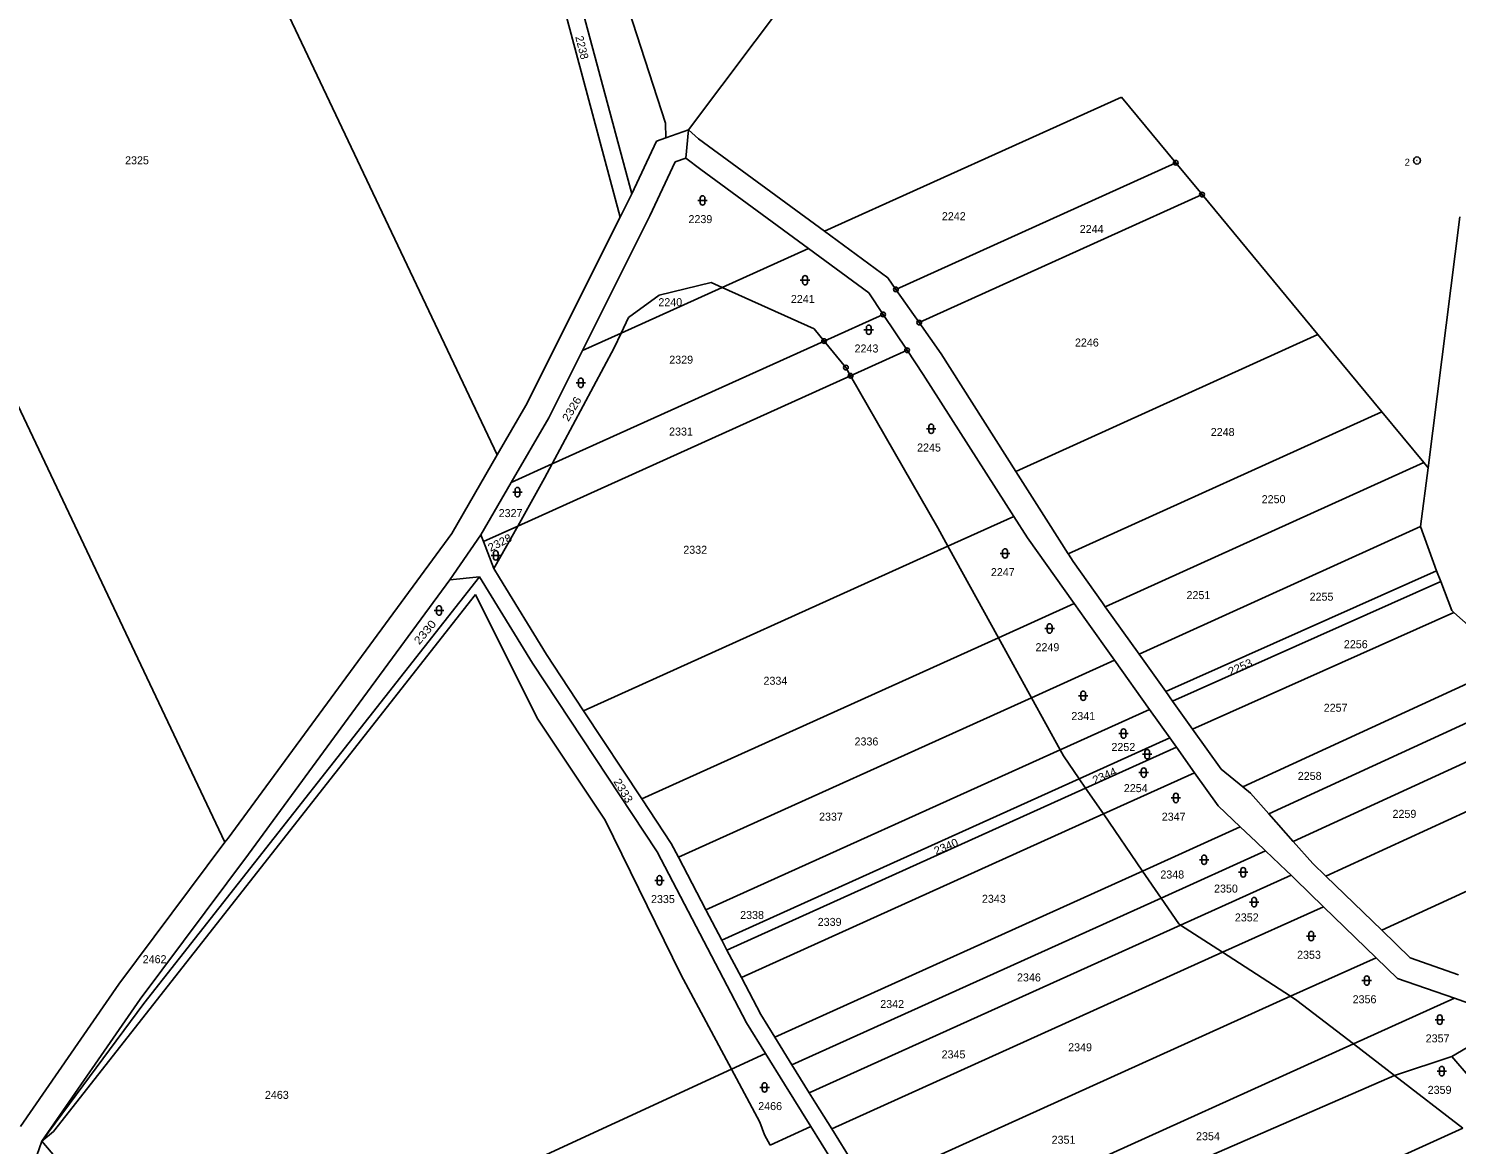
# Model space of a CAD drawing. Extents: x -606517 to -602431, y -1183120 to -1179397.
# Drawn here: x -605326.3 to -605022.9, y -1180737.7 to -1180500.6 of the extents above; entities that cross this region are included whole.
import ezdxf
from ezdxf.enums import TextEntityAlignment as Align

# ---------------------------------------------------------------- set-up
doc = ezdxf.new("R2010")
doc.units = 0
doc.header["$LTSCALE"] = 0.68
for name, color, linetype, lineweight in [('1', 7, 'Continuous', 25), ('3', 7, 'Continuous', 25), ('8', 7, 'Continuous', 25)]:
    doc.layers.add(name, color=color, linetype=linetype, lineweight=lineweight)
doc.layers.add('2', color=7, linetype='Continuous')

msp = doc.modelspace()

# ---------------------------------------------------------------- linework, layer by layer
at = {"layer": '1'}
for p, q in [((-605226.69, -1180591.17), (-605304.36, -1180427.32)), ((-605126.51, -1180442.54), (-605186.02, -1180522.13)), ((-605190.97, -1180520.67), (-605210.04, -1180461.72)), ((-605219.84, -1180468.76), (-605200.54, -1180540.66)), ((-605198.12, -1180535.69), (-605208.88, -1180495.66)), ((-605094.07, -1180515.16), (-605157.16, -1180543.67)), ((-605082.54, -1180529.1), (-605094.07, -1180515.16)), ((-605190.84, -1180523.78), (-605190.97, -1180520.67)), ((-605190.84, -1180523.78), (-605192.87, -1180524.48)), ((-605186.02, -1180522.13), (-605190.84, -1180523.78)), ((-605186.64, -1180528.15), (-605186.02, -1180522.13)), ((-605186.02, -1180522.13), (-605183.96, -1180523.98)), ((-605183.96, -1180523.98), (-605157.16, -1180543.67)), ((-605192.87, -1180524.48), (-605198.12, -1180535.69)), ((-605188.88, -1180528.92), (-605194.26, -1180540.41)), ((-605186.64, -1180528.15), (-605188.88, -1180528.92)), ((-605183.45, -1180530.5), (-605186.64, -1180528.15)), ((-605141.99, -1180556.01), (-605082.54, -1180529.1)), ((-605082.54, -1180529.1), (-605076.96, -1180535.85)), ((-605160.59, -1180547.32), (-605183.45, -1180530.5)), ((-605200.54, -1180540.66), (-605198.12, -1180535.69)), ((-605137.04, -1180563.05), (-605076.96, -1180535.85)), ((-605076.96, -1180535.85), (-605052.33, -1180565.62)), ((-605200.54, -1180540.66), (-605220.6, -1180580.66)), ((-605194.26, -1180540.41), (-605208.6, -1180569.01)), ((-605028.93, -1180593.91), (-605022.19, -1180540.62)), ((-605157.16, -1180543.67), (-605143.74, -1180553.52)), ((-605160.59, -1180547.32), (-605178.9, -1180555.59)), ((-605147.75, -1180556.77), (-605160.59, -1180547.32)), ((-605143.74, -1180553.52), (-605141.99, -1180556.01)), ((-605178.9, -1180555.59), (-605200.39, -1180565.3)), ((-605192.28, -1180557.21), (-605198.81, -1180561.95)), ((-605181.25, -1180554.53), (-605192.28, -1180557.21)), ((-605178.9, -1180555.59), (-605181.25, -1180554.53)), ((-605159.35, -1180564.41), (-605178.9, -1180555.59)), ((-605144.71, -1180561.33), (-605147.75, -1180556.77)), ((-605137.04, -1180563.05), (-605141.99, -1180556.01)), ((-605284.53, -1180673.49), (-605337.03, -1180562.74)), ((-605198.81, -1180561.95), (-605200.39, -1180565.3)), ((-605144.71, -1180561.33), (-605157.24, -1180566.99)), ((-605139.63, -1180568.93), (-605144.71, -1180561.33)), ((-605132.37, -1180569.7), (-605137.04, -1180563.05)), ((-605208.6, -1180569.01), (-605200.39, -1180565.3)), ((-605200.39, -1180565.3), (-605201.85, -1180568.41)), ((-605157.24, -1180566.99), (-605159.35, -1180564.41)), ((-605116.52, -1180594.68), (-605052.33, -1180565.62)), ((-605052.33, -1180565.62), (-605038.75, -1180582.03)), ((-605208.6, -1180569.01), (-605215.76, -1180583.28)), ((-605157.24, -1180566.99), (-605215.03, -1180593.1)), ((-605201.85, -1180568.41), (-605215.03, -1180593.1)), ((-605152.62, -1180572.62), (-605157.24, -1180566.99)), ((-605139.63, -1180568.93), (-605151.63, -1180574.35)), ((-605136.18, -1180574.09), (-605139.63, -1180568.93)), ((-605151.63, -1180574.35), (-605152.62, -1180572.62)), ((-605116.52, -1180594.68), (-605132.37, -1180569.7)), ((-605151.63, -1180574.35), (-605222.33, -1180606.29)), ((-605133.11, -1180606.66), (-605151.63, -1180574.35)), ((-605116.94, -1180604.27), (-605136.18, -1180574.09)), ((-605220.6, -1180580.66), (-605226.69, -1180591.17)), ((-605215.76, -1180583.28), (-605223.71, -1180597.02)), ((-605105.38, -1180612.2), (-605038.75, -1180582.03)), ((-605038.75, -1180582.03), (-605029.84, -1180592.8)), ((-605226.69, -1180591.17), (-605236.37, -1180607.9)), ((-605215.03, -1180593.1), (-605223.71, -1180597.02)), ((-605215.03, -1180593.1), (-605216.63, -1180596.09)), ((-605097.5, -1180623.43), (-605029.84, -1180592.8)), ((-605028.93, -1180593.91), (-605030.52, -1180606.42)), ((-605029.84, -1180592.8), (-605028.93, -1180593.91)), ((-605216.63, -1180596.09), (-605222.33, -1180606.29)), ((-605109.56, -1180605.64), (-605116.52, -1180594.68)), ((-605223.71, -1180597.02), (-605230.17, -1180608.18)), ((-605116.94, -1180604.27), (-605130.94, -1180610.59)), ((-605114.03, -1180608.83), (-605116.94, -1180604.27)), ((-605105.38, -1180612.2), (-605109.56, -1180605.64)), ((-605236.37, -1180607.9), (-605260.43, -1180640.69)), ((-605236.73, -1180617.7), (-605230.17, -1180608.18)), ((-605230.17, -1180608.18), (-605229.63, -1180609.59)), ((-605229.63, -1180609.59), (-605222.33, -1180606.29)), ((-605222.33, -1180606.29), (-605227.39, -1180615.34)), ((-605130.94, -1180610.59), (-605133.11, -1180606.66)), ((-605104.11, -1180622.77), (-605114.03, -1180608.83)), ((-605030.52, -1180606.42), (-605090.33, -1180633.5)), ((-605030.52, -1180606.42), (-605027.12, -1180615.83)), ((-605229.63, -1180609.59), (-605227.39, -1180615.34)), ((-605208.33, -1180645.55), (-605130.94, -1180610.59)), ((-605130.94, -1180610.59), (-605120.21, -1180630.04)), ((-605105.35, -1180612.24), (-605105.38, -1180612.2)), ((-605104.35, -1180613.81), (-605105.35, -1180612.24)), ((-605098.08, -1180622.62), (-605104.35, -1180613.81)), ((-605301.78, -1180707.72), (-605230.45, -1180617.06)), ((-605236.73, -1180617.7), (-605255.99, -1180643.95)), ((-605230.45, -1180617.06), (-605236.73, -1180617.7)), ((-605230.45, -1180617.06), (-605219.17, -1180635.46)), ((-605227.39, -1180615.34), (-605226.18, -1180617.32)), ((-605226.18, -1180617.32), (-605216.22, -1180633.58)), ((-605084.65, -1180641.48), (-605027.12, -1180615.83)), ((-605083.21, -1180643.51), (-605026.25, -1180618.11)), ((-605027.12, -1180615.83), (-605026.25, -1180618.11)), ((-605026.25, -1180618.11), (-605023.91, -1180624.27)), ((-605231.28, -1180620.82), (-605320.99, -1180734.92)), ((-605218.18, -1180647.1), (-605231.28, -1180620.82)), ((-605104.11, -1180622.77), (-605120.21, -1180630.04)), ((-605101.68, -1180626.18), (-605104.11, -1180622.77)), ((-605097.5, -1180623.43), (-605098.08, -1180622.62)), ((-605090.33, -1180633.5), (-605097.5, -1180623.43)), ((-605023.91, -1180624.27), (-605023.45, -1180624.68)), ((-605095.55, -1180634.79), (-605101.68, -1180626.18)), ((-605078.98, -1180649.44), (-605023.45, -1180624.68)), ((-605023.45, -1180624.68), (-605011.3, -1180635.5)), ((-605120.21, -1180630.04), (-605195.98, -1180664.27)), ((-605113.19, -1180642.76), (-605120.21, -1180630.04)), ((-605219.17, -1180635.46), (-605192.74, -1180675.55)), ((-605216.22, -1180633.58), (-605208.33, -1180645.55)), ((-605113.19, -1180642.76), (-605095.55, -1180634.79)), ((-605088.1, -1180645.27), (-605095.55, -1180634.79)), ((-605084.65, -1180641.48), (-605090.33, -1180633.5)), ((-605068.31, -1180661.72), (-605011.3, -1180635.5)), ((-605260.43, -1180640.69), (-605283.88, -1180672.63)), ((-605083.21, -1180643.51), (-605084.65, -1180641.48)), ((-605062.78, -1180667.45), (-605005.17, -1180640.96)), ((-605255.99, -1180643.95), (-605279.53, -1180676.02)), ((-605113.19, -1180642.76), (-605188.21, -1180676.65)), ((-605107.08, -1180653.84), (-605113.19, -1180642.76)), ((-605088.1, -1180645.27), (-605107.08, -1180653.84)), ((-605083.79, -1180651.32), (-605088.1, -1180645.27)), ((-605078.98, -1180649.44), (-605083.21, -1180643.51)), ((-605203.78, -1180668.79), (-605218.18, -1180647.1)), ((-605208.33, -1180645.55), (-605195.98, -1180664.27)), ((-605057.57, -1180673.32), (-604999.05, -1180646.41)), ((-605083.79, -1180651.32), (-605103.03, -1180660.01)), ((-605082.41, -1180653.26), (-605083.79, -1180651.32)), ((-605072.92, -1180657.96), (-605078.98, -1180649.44)), ((-605182.35, -1180687.85), (-605107.08, -1180653.84)), ((-605107.08, -1180653.84), (-605106.37, -1180655.13)), ((-605082.41, -1180653.26), (-605101.68, -1180661.97)), ((-605078.53, -1180658.71), (-605082.41, -1180653.26)), ((-605050.64, -1180680.69), (-604991.23, -1180653.38)), ((-605106.37, -1180655.13), (-605103.03, -1180660.01)), ((-605103.03, -1180660.01), (-605178.97, -1180694.32)), ((-605103.03, -1180660.01), (-605101.68, -1180661.97)), ((-605097.91, -1180667.47), (-605078.53, -1180658.71)), ((-605073.54, -1180665.72), (-605078.53, -1180658.71)), ((-605068.31, -1180661.72), (-605072.92, -1180657.96)), ((-605101.68, -1180661.97), (-605177.88, -1180696.39)), ((-605097.91, -1180667.47), (-605101.68, -1180661.97)), ((-605066.66, -1180663.07), (-605068.31, -1180661.72)), ((-605062.78, -1180667.45), (-605066.66, -1180663.07)), ((-605195.98, -1180664.27), (-605189.72, -1180673.77)), ((-605068.82, -1180670.22), (-605073.54, -1180665.72)), ((-605038.77, -1180692.19), (-604978.67, -1180664.56)), ((-605187.67, -1180701.61), (-605203.78, -1180668.79)), ((-605174.83, -1180702.22), (-605097.91, -1180667.47)), ((-605089.59, -1180679.61), (-605097.91, -1180667.47)), ((-605057.57, -1180673.32), (-605062.78, -1180667.45)), ((-605283.88, -1180672.63), (-605284.53, -1180673.49)), ((-605068.82, -1180670.22), (-605089.59, -1180679.61)), ((-605065.47, -1180673.41), (-605068.82, -1180670.22)), ((-605307.05, -1180703.62), (-605284.53, -1180673.49)), ((-605192.74, -1180675.55), (-605173.75, -1180711.84)), ((-605189.72, -1180673.77), (-605188.21, -1180676.65)), ((-605063.46, -1180675.33), (-605065.47, -1180673.41)), ((-605059, -1180679.57), (-605063.46, -1180675.33)), ((-605053.45, -1180677.97), (-605057.57, -1180673.32)), ((-605279.53, -1180676.02), (-605302.56, -1180706.8)), ((-605188.21, -1180676.65), (-605182.35, -1180687.85)), ((-605050.64, -1180680.69), (-605053.45, -1180677.97)), ((-605089.59, -1180679.61), (-605167.72, -1180714.91)), ((-605085.65, -1180685.35), (-605089.59, -1180679.61)), ((-605058.05, -1180680.48), (-605059, -1180679.57)), ((-605057.18, -1180681.31), (-605058.05, -1180680.48)), ((-605051.13, -1180687.17), (-605057.18, -1180681.31)), ((-605038.77, -1180692.19), (-605050.64, -1180680.69)), ((-605182.35, -1180687.85), (-605178.97, -1180694.32)), ((-605081.89, -1180690.84), (-605085.65, -1180685.35)), ((-605051.13, -1180687.17), (-605072.59, -1180696.86)), ((-605039.95, -1180698.01), (-605051.13, -1180687.17)), ((-605081.52, -1180691.08), (-605081.89, -1180690.84)), ((-605072.59, -1180696.86), (-605081.52, -1180691.08)), ((-605032.71, -1180698.07), (-605038.77, -1180692.19)), ((-605178.97, -1180694.32), (-605177.88, -1180696.39)), ((-605177.88, -1180696.39), (-605174.83, -1180702.22)), ((-605155.63, -1180734.38), (-605072.59, -1180696.86)), ((-605072.59, -1180696.86), (-605058.13, -1180706.22)), ((-605058.13, -1180706.22), (-605039.95, -1180698.01)), ((-605035.4, -1180702.43), (-605039.95, -1180698.01)), ((-605022.49, -1180701.63), (-605032.71, -1180698.07)), ((-605176.91, -1180721.73), (-605187.67, -1180701.61)), ((-605174.83, -1180702.22), (-605170.71, -1180710.1)), ((-605023.32, -1180706.64), (-605035.4, -1180702.43)), ((-605327.95, -1180733.85), (-605307.05, -1180703.62)), ((-605302.56, -1180706.8), (-605323.42, -1180736.98)), ((-605323.42, -1180736.98), (-605301.78, -1180707.72)), ((-605058.13, -1180706.22), (-605147.9, -1180746.78)), ((-605056.8, -1180707.08), (-605058.13, -1180706.22)), ((-605044.77, -1180716.33), (-605056.8, -1180707.08)), ((-605023.32, -1180706.64), (-605044.77, -1180716.33)), ((-605017.56, -1180708.65), (-605023.32, -1180706.64)), ((-605173.75, -1180711.84), (-605169.67, -1180718.4)), ((-605170.71, -1180710.1), (-605167.72, -1180714.91)), ((-605167.72, -1180714.91), (-605164.07, -1180720.78)), ((-605017.03, -1180714.95), (-605023.9, -1180718.99)), ((-605044.77, -1180716.33), (-605139.99, -1180759.35)), ((-605036.05, -1180723.03), (-605044.77, -1180716.33)), ((-605169.67, -1180718.4), (-605176.91, -1180721.73)), ((-605165.63, -1180724.9), (-605169.67, -1180718.4)), ((-605164.07, -1180720.78), (-605160.39, -1180726.71)), ((-605023.9, -1180718.99), (-605036.05, -1180723.03)), ((-605023.9, -1180718.99), (-605013.83, -1180730.73)), ((-605176.91, -1180721.73), (-605300.37, -1180778.51)), ((-605170.91, -1180732.95), (-605176.91, -1180721.73)), ((-605135.59, -1180766.34), (-605036.05, -1180723.03)), ((-605036.05, -1180723.03), (-605021.53, -1180734.2)), ((-605160.07, -1180733.87), (-605165.63, -1180724.9)), ((-605160.39, -1180726.71), (-605159, -1180728.96)), ((-605159, -1180728.96), (-605155.63, -1180734.38)), ((-605169.88, -1180735.68), (-605170.91, -1180732.95)), ((-605320.99, -1180734.92), (-605323.42, -1180736.98)), ((-605168.67, -1180737.82), (-605169.88, -1180735.68)), ((-605160.07, -1180733.87), (-605168.67, -1180737.82)), ((-605152.59, -1180745.9), (-605160.07, -1180733.87)), ((-605155.63, -1180734.38), (-605149.62, -1180744.04)), ((-605021.53, -1180734.2), (-605125.99, -1180781.59)), ((-605326.18, -1180744.86), (-605323.42, -1180736.98)), ((-605314.62, -1180747.36), (-605323.42, -1180736.98))]:
    msp.add_line(p, q, dxfattribs=at)
for points in [[(-605063.46, -1180675.33), (-605085.65, -1180685.35), (-605164.07, -1180720.78)], [(-605058.05, -1180680.48), (-605081.52, -1180691.08), (-605160.39, -1180726.71)]]:
    msp.add_lwpolyline(points, dxfattribs=at)
at = {"layer": '3'}
for p, q in [((-605184.061, -1180537.101), (-605182.059, -1180537.101)), ((-605183.561, -1180536.601), (-605183.561, -1180537.602)), ((-605182.559, -1180537.602), (-605182.559, -1180536.601)), ((-605162.301, -1180554.071), (-605160.299, -1180554.071)), ((-605161.801, -1180553.571), (-605161.801, -1180554.572)), ((-605160.799, -1180554.572), (-605160.799, -1180553.571)), ((-605148.771, -1180564.591), (-605146.769, -1180564.591)), ((-605148.271, -1180564.091), (-605148.271, -1180565.092)), ((-605147.269, -1180565.092), (-605147.269, -1180564.091)), ((-605209.441, -1180575.361), (-605209.441, -1180576.362)), ((-605208.439, -1180576.362), (-605208.439, -1180575.361)), ((-605209.941, -1180575.861), (-605207.939, -1180575.861)), ((-605135.491, -1180585.631), (-605133.489, -1180585.631)), ((-605134.991, -1180585.131), (-605134.991, -1180586.132)), ((-605133.989, -1180586.132), (-605133.989, -1180585.131)), ((-605223.401, -1180599.091), (-605221.399, -1180599.091)), ((-605222.901, -1180598.591), (-605222.901, -1180599.592)), ((-605221.899, -1180599.592), (-605221.899, -1180598.591)), ((-605227.501, -1180612.021), (-605227.501, -1180613.022)), ((-605226.499, -1180613.022), (-605226.499, -1180612.021)), ((-605119.811, -1180612.111), (-605117.809, -1180612.111)), ((-605119.311, -1180611.611), (-605119.311, -1180612.612)), ((-605118.309, -1180612.612), (-605118.309, -1180611.611)), ((-605228.001, -1180612.521), (-605225.999, -1180612.521)), ((-605240.061, -1180624.241), (-605238.059, -1180624.241)), ((-605239.561, -1180623.741), (-605239.561, -1180624.742)), ((-605238.559, -1180624.742), (-605238.559, -1180623.741)), ((-605110.331, -1180628.061), (-605108.329, -1180628.061)), ((-605109.831, -1180627.561), (-605109.831, -1180628.562)), ((-605108.829, -1180628.562), (-605108.829, -1180627.561)), ((-605103.191, -1180642.351), (-605101.189, -1180642.351)), ((-605102.691, -1180641.851), (-605102.691, -1180642.852)), ((-605101.689, -1180642.852), (-605101.689, -1180641.851)), ((-605094.631, -1180650.391), (-605092.629, -1180650.391)), ((-605094.131, -1180649.891), (-605094.131, -1180650.892)), ((-605093.129, -1180650.892), (-605093.129, -1180649.891)), ((-605089.101, -1180654.281), (-605089.101, -1180655.282)), ((-605088.099, -1180655.282), (-605088.099, -1180654.281)), ((-605089.601, -1180654.781), (-605087.599, -1180654.781)), ((-605090.351, -1180658.691), (-605088.349, -1180658.691)), ((-605089.851, -1180658.191), (-605089.851, -1180659.192)), ((-605088.849, -1180659.192), (-605088.849, -1180658.191)), ((-605083.011, -1180663.571), (-605083.011, -1180664.572)), ((-605082.009, -1180664.572), (-605082.009, -1180663.571)), ((-605083.511, -1180664.071), (-605081.509, -1180664.071)), ((-605077.521, -1180677.211), (-605075.519, -1180677.211)), ((-605077.021, -1180676.711), (-605077.021, -1180677.712)), ((-605076.019, -1180677.712), (-605076.019, -1180676.711)), ((-605193.231, -1180681.581), (-605191.229, -1180681.581)), ((-605192.731, -1180681.081), (-605192.731, -1180682.082)), ((-605191.729, -1180682.082), (-605191.729, -1180681.081)), ((-605069.201, -1180679.871), (-605067.199, -1180679.871)), ((-605068.701, -1180679.371), (-605068.701, -1180680.372)), ((-605067.699, -1180680.372), (-605067.699, -1180679.371)), ((-605066.901, -1180686.211), (-605064.899, -1180686.211)), ((-605066.401, -1180685.711), (-605066.401, -1180686.712)), ((-605065.399, -1180686.712), (-605065.399, -1180685.711)), ((-605054.761, -1180693.421), (-605052.759, -1180693.421)), ((-605054.261, -1180692.921), (-605054.261, -1180693.922)), ((-605053.259, -1180693.922), (-605053.259, -1180692.921)), ((-605042.971, -1180702.871), (-605040.969, -1180702.871)), ((-605042.471, -1180702.371), (-605042.471, -1180703.372)), ((-605041.469, -1180703.372), (-605041.469, -1180702.371)), ((-605027.441, -1180711.181), (-605025.439, -1180711.181)), ((-605026.941, -1180710.681), (-605026.941, -1180711.682)), ((-605025.939, -1180711.682), (-605025.939, -1180710.681)), ((-605027.011, -1180722.121), (-605025.009, -1180722.121)), ((-605026.511, -1180721.621), (-605026.511, -1180722.622)), ((-605025.509, -1180722.622), (-605025.509, -1180721.621)), ((-605170.881, -1180725.571), (-605168.879, -1180725.571)), ((-605170.381, -1180725.071), (-605170.381, -1180726.072)), ((-605169.379, -1180726.072), (-605169.379, -1180725.071))]:
    msp.add_line(p, q, dxfattribs=at)
for centre, start, end in [((-605183.06, -1180536.6009), 0, 180), ((-605183.06, -1180537.6009), 180, 359.98789), ((-605161.3, -1180553.5709), 0, 180), ((-605161.3, -1180554.5709), 180, 359.98789), ((-605147.77, -1180564.0909), 0, 180), ((-605147.77, -1180565.0909), 180, 359.98789), ((-605208.94, -1180575.3609), 0, 180), ((-605208.94, -1180576.3609), 180, 359.98789), ((-605134.49, -1180585.1309), 0, 180), ((-605134.49, -1180586.1309), 180, 359.98789), ((-605222.4, -1180598.5909), 0, 180), ((-605222.4, -1180599.5909), 180, 359.98789), ((-605227, -1180612.0209), 0, 180), ((-605118.81, -1180611.6109), 0, 180), ((-605227, -1180613.0209), 180, 359.98789), ((-605118.81, -1180612.6109), 180, 359.98789), ((-605239.06, -1180623.7409), 0, 180), ((-605239.06, -1180624.7409), 180, 359.98789), ((-605109.33, -1180627.5609), 0, 180), ((-605109.33, -1180628.5609), 180, 359.98789), ((-605102.19, -1180641.8509), 0, 180), ((-605102.19, -1180642.8509), 180, 359.98789), ((-605093.63, -1180649.8909), 0, 180), ((-605093.63, -1180650.8909), 180, 359.98789), ((-605088.6, -1180654.2809), 0, 180), ((-605088.6, -1180655.2809), 180, 359.98789), ((-605089.35, -1180658.1909), 0, 180), ((-605089.35, -1180659.1909), 180, 359.98789), ((-605082.51, -1180663.5709), 0, 180), ((-605082.51, -1180664.5709), 180, 359.98789), ((-605076.52, -1180676.7109), 0, 180), ((-605076.52, -1180677.7109), 180, 359.98789), ((-605068.2, -1180679.3709), 0, 180), ((-605192.23, -1180681.0809), 0, 180), ((-605068.2, -1180680.3709), 180, 359.98789), ((-605192.23, -1180682.0809), 180, 359.98789), ((-605065.9, -1180685.7109), 0, 180), ((-605065.9, -1180686.7109), 180, 359.98789), ((-605053.76, -1180692.9209), 0, 180), ((-605053.76, -1180693.9209), 180, 359.98789), ((-605041.97, -1180702.3709), 0, 180), ((-605041.97, -1180703.3709), 180, 359.98789), ((-605026.44, -1180710.6809), 0, 180), ((-605026.44, -1180711.6809), 180, 359.98789), ((-605026.01, -1180721.6209), 0, 180), ((-605026.01, -1180722.6209), 180, 359.98789), ((-605169.88, -1180725.0709), 0, 180), ((-605169.88, -1180726.0709), 180, 359.98789)]:
    msp.add_arc(centre, 0.5, start, end, dxfattribs=at)
at = {"layer": '8'}
for centre, radius in [((-605082.54, -1180529.0999), 0.5), ((-605082.54, -1180529.0999), 0.0303), ((-605031.29, -1180528.6198), 0.75), ((-605031.29, -1180528.6198), 0.03), ((-605076.96, -1180535.8499), 0.5), ((-605076.96, -1180535.8499), 0.0303), ((-605141.99, -1180556.0099), 0.5), ((-605141.99, -1180556.0099), 0.0303), ((-605144.71, -1180561.3299), 0.5), ((-605144.71, -1180561.3299), 0.0303), ((-605137.04, -1180563.0499), 0.5), ((-605137.04, -1180563.0499), 0.0303), ((-605157.24, -1180566.9899), 0.5), ((-605157.24, -1180566.9899), 0.0303), ((-605139.63, -1180568.9299), 0.5), ((-605139.63, -1180568.9299), 0.0303), ((-605152.62, -1180572.6199), 0.5), ((-605152.62, -1180572.6199), 0.0303), ((-605151.63, -1180574.3499), 0.5), ((-605151.63, -1180574.3499), 0.0303)]:
    msp.add_circle(centre, radius, dxfattribs=at)

# ---------------------------------------------------------------- texts
at = {"layer": '2'}
msp.add_text('2238', height=1.7, rotation=284, dxfattribs=at).set_placement((-605210.112, -1180502.372))
for s, p in [('2325', (-605305.75, -1180529.425)), ('2239', (-605186.06, -1180541.925)), ('2242', (-605132.22, -1180541.305)), ('2244', (-605102.94, -1180544.025)), ('2241', (-605164.3, -1180558.895)), ('2240', (-605192.46, -1180559.575)), ('2246', (-605103.95, -1180568.145)), ('2243', (-605150.77, -1180569.415)), ('2329', (-605190.14, -1180571.795)), ('2331', (-605190.18, -1180587.065)), ('2248', (-605075.1, -1180587.165)), ('2245', (-605137.49, -1180590.455)), ('2250', (-605064.28, -1180601.435)), ('2327', (-605226.38, -1180604.395)), ('2332', (-605187.16, -1180612.185)), ('2247', (-605121.81, -1180616.935)), ('2251', (-605080.25, -1180621.815)), ('2255', (-605054.1, -1180622.155)), ('2249', (-605112.33, -1180632.885)), ('2256', (-605046.82, -1180632.255)), ('2334', (-605170.12, -1180640.015)), ('2257', (-605051.1, -1180645.755)), ('2341', (-605104.72, -1180647.515)), ('2336', (-605150.78, -1180652.915)), ('2252', (-605096.2, -1180654.085)), ('2258', (-605056.61, -1180660.235)), ('2254', (-605093.57, -1180662.835)), ('2259', (-605036.48, -1180668.295)), ('2337', (-605158.32, -1180668.895)), ('2347', (-605085.51, -1180668.895)), ('2348', (-605085.81, -1180681.185)), ('2335', (-605194.02, -1180686.405)), ('2343', (-605123.71, -1180686.345)), ('2350', (-605074.4, -1180684.175)), ('2338', (-605175.08, -1180689.785)), ('2339', (-605158.6, -1180691.255)), ('2352', (-605069.98, -1180690.305)), ('2353', (-605056.76, -1180698.245)), ('2462', (-605302.01, -1180699.185)), ('2346', (-605116.26, -1180703.055)), ('2356', (-605044.96, -1180707.695)), ('2342', (-605145.32, -1180708.705)), ('2357', (-605029.44, -1180716.005)), ('2345', (-605132.28, -1180719.405)), ('2349', (-605105.39, -1180717.895)), ('2463', (-605276.04, -1180728.015)), ('2359', (-605029.01, -1180726.945)), ('2466', (-605171.24, -1180730.395)), ('2351', (-605108.91, -1180737.545)), ('2354', (-605078.22, -1180736.795))]:
    msp.add_text(s, height=1.7, dxfattribs=at).set_placement(p)
for s, rotation, width, p in [('2326', 59, 1.1, (-605211.565, -1180584.218)), ('2328', 27, 1.05, (-605228.127, -1180611.788)), ('2330', 50, 1.15, (-605243.254, -1180631.623)), ('2253', 24, 1.05, (-605070.927, -1180638.108)), ('2344', 24, 1.05, (-605099.757, -1180661.188)), ('2333', 301, 1.1, (-605202.064, -1180660.568)), ('2340', 23, 1.05, (-605133.463, -1180676.221))]:
    msp.add_text(s, height=1.7, rotation=rotation, dxfattribs=dict(at, width=width)).set_placement(p)
at = {"layer": '8'}
msp.add_text('2', height=1.5, dxfattribs=at).set_placement((-605032.79, -1180529.737), align=Align.RIGHT)

doc.saveas('drawing.dxf')
